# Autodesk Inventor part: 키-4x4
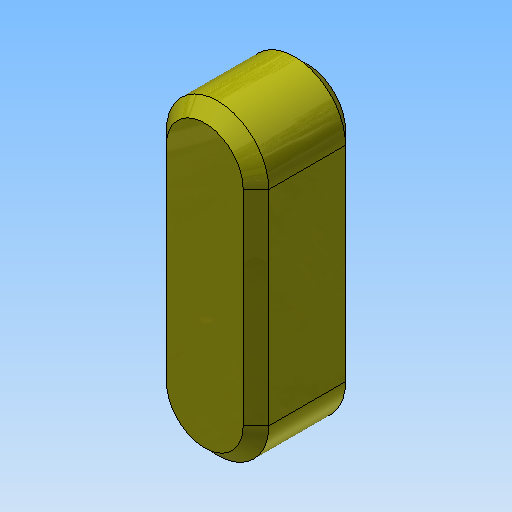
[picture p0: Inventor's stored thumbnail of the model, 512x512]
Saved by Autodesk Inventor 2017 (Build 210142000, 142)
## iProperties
Created: 2015-12
Part Number: 키-4x4
Document SubType Name: Modeling
Designer: mdu
Density: 7.86 g/cm^3
Material: 강철, 연강
Mass: 1.34709 g
Surface Area: 1.86014 cm^2
Volume: 0.171386 cm^3
Appearance: 노란색
Author: mdu
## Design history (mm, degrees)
sketch "스케치1"
  geometry: L1 (-2, -10)-(-2, -2) reference; L2 (2, -2)-(2, -10) reference; A1 r 2 centre (0, -2) between (2, -2) and (-2, -2) reference; A2 r 2 centre (0, -10) between (-2, -10) and (2, -10) reference; 1 further point
extrude "돌출1" new body sketch "스케치1" distance "d0" = 4; taper "d1" = 0 deg
chamfer "모따기1" distance "d2" = 0.5; stored, may be unused: second distance "d3" = 2, angle "d4" = 45 deg
node "솔리드1"
node "참조1"
